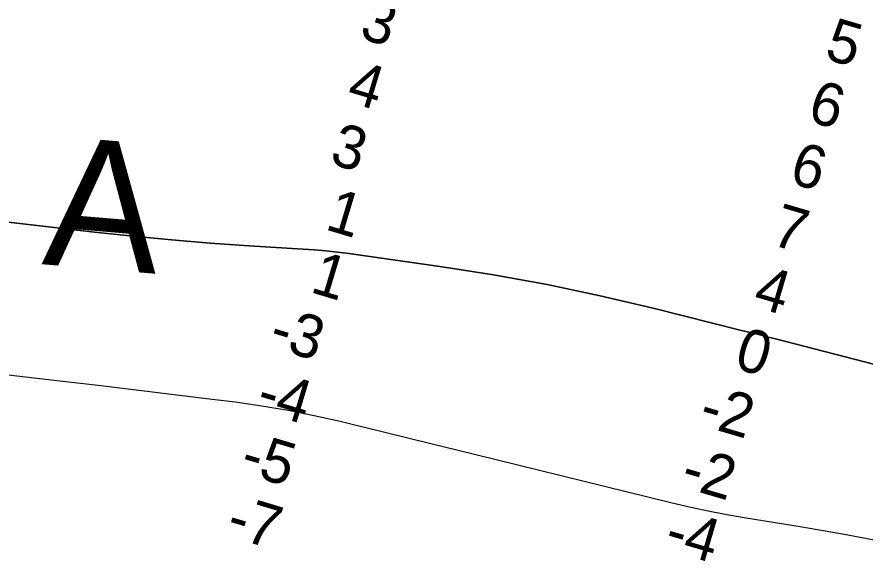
# Model space of a CAD drawing. Extents: x 3192986 to 3230865, y 867483 to 892886.
# Drawn here: x 3210713 to 3212029, y 877832 to 878676 of the extents above; entities that cross this region are included whole.
import ezdxf

# ---------------------------------------------------------------- set-up
doc = ezdxf.new("R2010")
doc.units = 0
for name, color, linetype in [('V-RIVR-IDEN', 7, 'Continuous'), ('V-RIVR-RANG', 7, 'Continuous'), ('V-TOPO-DPTH', 7, 'Continuous'), ('V-TOPO-MINR', 7, 'Continuous')]:
    doc.layers.add(name, color=color, linetype=linetype)

msp = doc.modelspace()

# ---------------------------------------------------------------- linework, layer by layer
at = {"layer": 'V-TOPO-DPTH'}
msp.add_lwpolyline([(3210600.7, 878369.1), (3210833.4, 878342.2), (3210893.1, 878335.8), (3210952.9, 878330), (3211012.8, 878325.2), (3211072.7, 878321.1), (3211157.2, 878316), (3211174.9, 878314.7), (3211192.6, 878313.1), (3211210.3, 878311.1), (3211227.9, 878308.9), (3211369.5, 878288.9), (3211452.8, 878275.8), (3211535.8, 878260.9), (3211618.2, 878243.5), (3211700.3, 878224.3), (3211837.8, 878189.8), (3211850.9, 878186.5), (3211864, 878183.2), (3211877.1, 878179.8), (3211890.2, 878176.5), (3212279.2, 878076.2)], dxfattribs=at)
msp.add_lwpolyline([(3210600.7, 878369.1), (3210833.4, 878342.2), (3210893.1, 878335.8), (3210952.9, 878330), (3211012.8, 878325.2), (3211072.7, 878321.1), (3211157.2, 878316), (3211174.9, 878314.7), (3211192.6, 878313.1), (3211210.3, 878311.1), (3211227.9, 878308.9), (3211369.5, 878288.9), (3211452.8, 878275.8), (3211535.8, 878260.9), (3211618.2, 878243.5), (3211700.3, 878224.3), (3211837.8, 878189.8), (3211850.9, 878186.5), (3211864, 878183.2), (3211877.1, 878179.8), (3211890.2, 878176.5), (3212279.2, 878076.2)], dxfattribs=at)
at = {"layer": 'V-TOPO-MINR'}
for points in [[(3212279.2, 878076.2), (3211890.2, 878176.5), (3211877.1, 878179.8), (3211864, 878183.2), (3211850.9, 878186.5), (3211837.8, 878189.8), (3211700.3, 878224.3), (3211618.2, 878243.5), (3211535.8, 878260.9), (3211452.8, 878275.8), (3211369.5, 878288.9), (3211227.9, 878308.9), (3211210.3, 878311.1), (3211192.6, 878313.1), (3211174.9, 878314.7), (3211157.2, 878316), (3211072.7, 878321.1), (3211012.8, 878325.2), (3210952.9, 878330), (3210893.1, 878335.8), (3210833.4, 878342.2), (3210600.7, 878369.1)], [(3212068.1, 877859.6), (3212000.2, 877872.4), (3211932.1, 877884.3), (3211841.6, 877899.1), (3211812.5, 877904.2), (3211783.4, 877909.8), (3211754.6, 877916), (3211725.8, 877922.7), (3211425.1, 877996.4), (3211376.6, 878008.3), (3211328.1, 878020.2), (3211279.6, 878032.1), (3211231.1, 878044.1), (3211214.7, 878048.2), (3211174.3, 878057.4), (3211133.8, 878065.6), (3211092.9, 878072.4), (3211051.9, 878078.2), (3211016.1, 878082.7), (3210957, 878089.9), (3210897.9, 878097), (3210838.8, 878104), (3210779.7, 878110.9), (3210579.1, 878134)]]:
    msp.add_lwpolyline(points, dxfattribs=at)

# ---------------------------------------------------------------- texts
at = {"layer": 'V-RIVR-IDEN'}
msp.add_text('A ', height=200, rotation=355.1906, dxfattribs=at).set_placement((3210750.6, 878292.5))
at = {"layer": 'V-RIVR-RANG'}
for s, rotation, p in [('3', 343.2811, (3211242.4, 878643.8)), ('5', 343.5731, (3211964.5, 878611.7)), ('4', 343.2811, (3211222.5, 878545.5)), ('6', 343.5731, (3211937.8, 878515.4)), ('3', 343.2811, (3211196.1, 878449.2)), ('6', 343.5731, (3211909.5, 878419.4)), ('1', 343.2811, (3211189.4, 878347)), ('7', 343.5731, (3211881.3, 878323.5)), ('1', 343.2811, (3211166.2, 878249.7)), ('4', 343.5731, (3211853.3, 878227.5)), ('-3', 343.2811, (3211101.4, 878165)), ('0', 343.5731, (3211824.1, 878131.8)), ('-4', 343.2811, (3211081.5, 878066.7)), ('-2', 343.5731, (3211768.8, 878043.9)), ('-5', 343.2811, (3211056.6, 877969.9)), ('-2', 343.5731, (3211740.6, 877948)), ('-7', 343.2811, (3211035, 877872.2)), ('-4', 343.5731, (3211715.1, 877851.2))]:
    msp.add_text(s, height=67, rotation=rotation, dxfattribs=at).set_placement(p)

doc.saveas('drawing.dxf')
